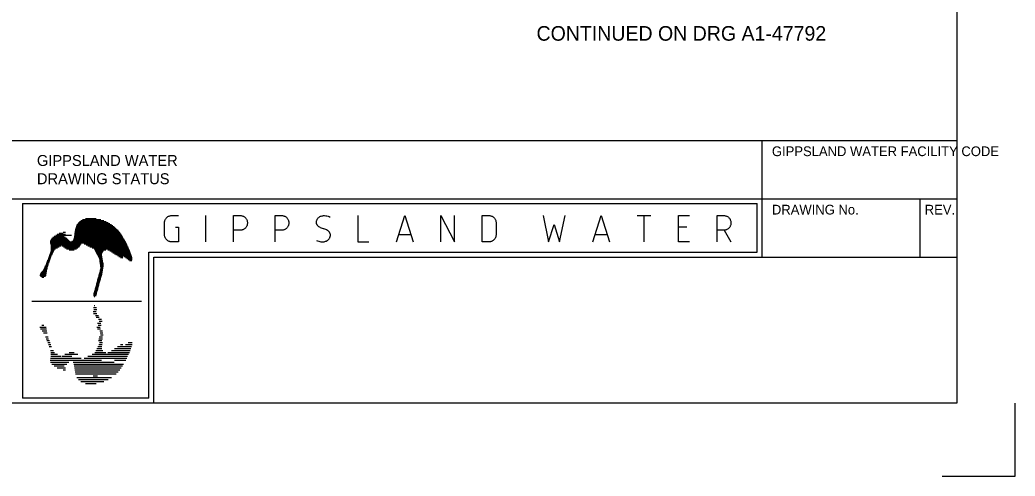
# Model space of a CAD drawing. Extents: x 0 to 841, y 0 to 594.
# Drawn here: x 636.5 to 841, y 0 to 93.8 of the extents above; entities that cross this region are included whole.
import ezdxf

# ---------------------------------------------------------------- set-up
doc = ezdxf.new("R2010")
doc.units = 0
doc.layers.add('A1BORDER', color=7, linetype='Continuous')
doc.layers.add('Level 1', color=7, linetype='Continuous')

msp = doc.modelspace()

# ---------------------------------------------------------------- linework, layer by layer
at = {"layer": 'A1BORDER'}
for p, q in [((829, 581), (829, 15)), ((592.5, 69), (829, 69)), ((789, 45), (789, 69)), ((28, 57), (829, 57)), ((637, 56), (788, 56)), ((637, 56), (637, 16)), ((788, 46), (788, 56)), ((821.5, 45), (821.5, 57)), ((648.03, 51.32), (655.85, 51.32)), ((648.12, 51.52), (655.59, 51.52)), ((648.23, 51.72), (655.31, 51.72)), ((648.37, 51.92), (655, 51.92)), ((648.53, 52.12), (654.64, 52.12)), ((648.74, 52.32), (654.24, 52.32)), ((649.02, 52.52), (653.76, 52.52)), ((649.39, 52.72), (653.15, 52.72)), ((650.01, 52.92), (652.2, 52.92)), ((643.26, 49.12), (645.9, 49.12)), ((643.54, 49.32), (645.57, 49.32)), ((643.85, 49.52), (647.09, 49.52)), ((644.18, 49.72), (645.89, 49.72)), ((644.54, 49.92), (645.36, 49.92)), ((645.37, 50.12), (645.86, 50.12)), ((647.63, 49.12), (657.68, 49.12)), ((647.66, 49.32), (657.57, 49.32)), ((647.69, 49.52), (657.44, 49.52)), ((647.71, 49.72), (657.31, 49.72)), ((647.75, 49.92), (657.17, 49.92)), ((647.78, 50.12), (657.02, 50.12)), ((647.81, 50.32), (656.86, 50.32)), ((647.85, 50.52), (656.69, 50.52)), ((647.88, 50.72), (656.5, 50.72)), ((647.91, 50.92), (656.3, 50.92)), ((647.96, 51.12), (656.08, 51.12)), ((642.73, 48.12), (658.25, 48.12)), ((642.74, 47.92), (658.35, 47.92)), ((642.75, 48.32), (646.79, 48.32)), ((642.79, 47.72), (649.08, 47.72)), ((642.81, 48.52), (646.55, 48.52)), ((642.83, 47.52), (648.95, 47.52)), ((642.85, 47.31), (644.88, 47.31)), ((642.87, 47.12), (644.57, 47.12)), ((642.9, 48.72), (646.37, 48.72)), ((643.04, 48.92), (646.16, 48.92)), ((645.14, 47.31), (648.83, 47.31)), ((645.49, 47.12), (648.67, 47.12)), ((647.19, 48.32), (658.14, 48.32)), ((647.42, 48.52), (658.03, 48.52)), ((647.54, 48.72), (657.92, 48.72)), ((647.61, 48.92), (657.8, 48.92)), ((649.72, 47.72), (658.45, 47.72)), ((650.12, 47.52), (658.55, 47.52)), ((650.48, 47.31), (658.64, 47.31)), ((650.87, 47.12), (658.73, 47.12)), ((642.43, 45.12), (642.9, 45.12)), ((642.5, 45.32), (643, 45.32)), ((642.57, 45.52), (643.1, 45.52)), ((642.65, 45.72), (643.2, 45.72)), ((642.72, 45.92), (643.3, 45.92)), ((642.79, 46.12), (643.4, 46.12)), ((642.84, 46.32), (643.5, 46.32)), ((642.87, 46.52), (643.6, 46.52)), ((642.88, 46.92), (644.23, 46.92)), ((642.88, 46.72), (643.83, 46.72)), ((645.76, 46.92), (648.42, 46.92)), ((646.05, 46.72), (648.11, 46.72)), ((646.62, 46.52), (647.67, 46.52)), ((651.36, 46.92), (658.82, 46.92)), ((651.76, 46.72), (658.9, 46.72)), ((651.88, 46.52), (654.15, 46.52)), ((651.99, 46.32), (653.71, 46.32)), ((652.1, 46.12), (653.52, 46.12)), ((652.2, 45.92), (653.4, 45.92)), ((652.31, 45.72), (653.33, 45.72)), ((652.41, 45.52), (653.31, 45.52)), ((652.5, 45.32), (653.34, 45.32)), ((652.6, 45.12), (653.38, 45.12)), ((654.57, 46.52), (658.99, 46.52)), ((655, 46.32), (659.07, 46.32)), ((655.31, 46.12), (659.14, 46.12)), ((655.62, 45.92), (659.22, 45.92)), ((655.93, 45.72), (659.29, 45.72)), ((656.24, 45.52), (659.35, 45.52)), ((656.55, 45.32), (659.42, 45.32)), ((656.86, 45.12), (657.74, 45.12)), ((657.91, 45.12), (659.48, 45.12)), ((663, 46), (788, 46)), ((663, 16), (663, 46)), ((664, 45), (829, 45)), ((664, 15), (664, 45)), ((641.64, 43.12), (642.25, 43.12)), ((641.73, 43.32), (642.3, 43.32)), ((641.82, 43.51), (642.35, 43.51)), ((641.91, 43.72), (642.41, 43.72)), ((641.99, 43.92), (642.48, 43.92)), ((642.06, 44.12), (642.55, 44.12)), ((642.13, 44.32), (642.62, 44.32)), ((642.21, 44.52), (642.69, 44.52)), ((642.28, 44.72), (642.76, 44.72)), ((642.35, 44.92), (642.83, 44.92)), ((652.69, 44.92), (653.41, 44.92)), ((652.78, 44.72), (653.44, 44.72)), ((652.83, 44.52), (653.48, 44.52)), ((652.86, 44.32), (653.53, 44.32)), ((652.89, 44.12), (653.57, 44.12)), ((652.91, 43.92), (653.62, 43.92)), ((652.94, 43.72), (653.67, 43.72)), ((652.97, 43.51), (653.71, 43.51)), ((653, 43.32), (653.69, 43.32)), ((653.02, 43.12), (653.67, 43.12)), ((657.17, 44.92), (657.68, 44.92)), ((657.51, 44.72), (657.54, 44.72)), ((658.19, 44.92), (659.54, 44.92)), ((658.47, 44.72), (659.59, 44.72)), ((658.75, 44.52), (659.58, 44.52)), ((659.02, 44.32), (659.47, 44.32)), ((640.62, 41.32), (641.88, 41.32)), ((640.63, 41.52), (641.93, 41.52)), ((640.72, 41.12), (641.73, 41.12)), ((640.73, 41.72), (641.95, 41.72)), ((640.9, 41.92), (641.97, 41.92)), ((641.03, 40.92), (641.43, 40.92)), ((641.1, 42.12), (642, 42.12)), ((641.25, 42.31), (642.04, 42.31)), ((641.37, 42.52), (642.09, 42.52)), ((641.46, 42.72), (642.15, 42.72)), ((641.55, 42.92), (642.2, 42.92)), ((652.57, 40.92), (653.2, 40.92)), ((652.63, 41.12), (653.26, 41.12)), ((652.68, 41.32), (653.31, 41.32)), ((652.74, 41.52), (653.37, 41.52)), ((652.79, 41.72), (653.41, 41.72)), ((652.85, 41.92), (653.45, 41.92)), ((652.9, 42.12), (653.49, 42.12)), ((652.95, 42.31), (653.53, 42.31)), ((652.99, 42.52), (653.57, 42.52)), ((653.03, 42.72), (653.61, 42.72)), ((653.05, 42.92), (653.64, 42.92)), ((652.03, 38.92), (652.66, 38.92)), ((652.09, 39.12), (652.72, 39.12)), ((652.14, 39.32), (652.77, 39.32)), ((652.2, 39.52), (652.82, 39.52)), ((652.25, 39.72), (652.88, 39.72)), ((652.3, 39.92), (652.93, 39.92)), ((652.36, 40.12), (652.99, 40.12)), ((652.41, 40.32), (653.04, 40.32)), ((652.47, 40.52), (653.1, 40.52)), ((652.52, 40.72), (653.15, 40.72)), ((651.63, 37.32), (652.23, 37.32)), ((651.64, 37.12), (652.17, 37.12)), ((651.65, 37.52), (652.28, 37.52)), ((651.71, 37.72), (652.34, 37.72)), ((651.76, 37.92), (652.39, 37.92)), ((651.79, 36.92), (651.9, 36.92)), ((651.82, 38.12), (652.44, 38.12)), ((651.87, 38.32), (652.5, 38.32)), ((651.92, 38.52), (652.55, 38.52)), ((651.98, 38.72), (652.61, 38.72)), ((638.93, 35.98), (661.47, 35.98)), ((651.79, 35.04), (651.9, 35.04)), ((651.54, 33.84), (652.17, 33.84)), ((651.63, 34.64), (652.23, 34.64)), ((651.65, 33.44), (652.28, 33.44)), ((651.71, 34.24), (652.34, 34.24)), ((652.03, 33.04), (652.66, 33.04)), ((641.03, 31.04), (641.43, 31.04)), ((652.14, 32.64), (652.77, 32.64)), ((652.47, 31.44), (653.1, 31.44)), ((652.57, 31.04), (653.2, 31.04)), ((652.66, 32.24), (653.29, 32.24)), ((652.77, 31.84), (653.4, 31.84)), ((640.62, 30.64), (641.88, 30.64)), ((640.73, 30.24), (641.95, 30.24)), ((641.1, 29.84), (642, 29.84)), ((641.37, 29.44), (642.09, 29.44)), ((641.73, 28.64), (642.3, 28.64)), ((652.34, 30.64), (652.97, 30.64)), ((652.45, 30.24), (653.07, 30.24)), ((652.77, 28.64), (653.46, 28.64)), ((652.9, 29.84), (653.49, 29.84)), ((652.99, 29.44), (653.57, 29.44)), ((653.05, 29.04), (653.64, 29.04)), ((641.91, 28.24), (642.41, 28.24)), ((642.06, 27.84), (642.55, 27.84)), ((642.21, 27.44), (642.69, 27.44)), ((642.35, 27.04), (642.83, 27.04)), ((642.5, 26.64), (643, 26.64)), ((652.5, 26.64), (653.34, 26.64)), ((652.66, 27.84), (653.35, 27.84)), ((652.69, 27.04), (653.41, 27.04)), ((652.72, 28.24), (653.44, 28.24)), ((652.83, 27.44), (653.48, 27.44)), ((656.55, 26.64), (659.42, 26.64)), ((657.17, 27.04), (657.68, 27.04)), ((658.19, 27.04), (659.54, 27.04)), ((658.75, 27.44), (659.58, 27.44)), ((642.79, 25.84), (643.4, 25.84)), ((642.85, 24.65), (644.88, 24.65)), ((642.87, 25.44), (643.6, 25.44)), ((642.88, 25.04), (644.23, 25.04)), ((645.14, 24.65), (647.18, 24.65)), ((645.76, 25.04), (648.42, 25.04)), ((646.62, 25.44), (647.67, 25.44)), ((650.48, 24.65), (658.64, 24.65)), ((651.36, 25.04), (658.82, 25.04)), ((651.88, 25.44), (654.15, 25.44)), ((652.1, 25.84), (653.52, 25.84)), ((652.31, 26.24), (653.33, 26.24)), ((654.57, 25.44), (658.99, 25.44)), ((655.31, 25.84), (659.14, 25.84)), ((655.93, 26.24), (659.29, 26.24)), ((642.73, 23.84), (653.27, 23.84)), ((642.79, 24.24), (649.08, 24.24)), ((642.81, 23.44), (646.55, 23.44)), ((643.04, 23.04), (646.16, 23.04)), ((643.54, 22.64), (645.57, 22.64)), ((647.42, 23.44), (655.89, 23.44)), ((647.61, 23.04), (657.8, 23.04)), ((647.66, 22.64), (657.57, 22.64)), ((649.72, 24.24), (658.45, 24.24)), ((655.94, 23.84), (658.25, 23.84)), ((644.18, 22.24), (645.89, 22.24)), ((645.37, 21.84), (645.86, 21.84)), ((647.71, 22.24), (657.31, 22.24)), ((647.78, 21.84), (657.02, 21.84)), ((647.85, 21.44), (656.69, 21.44)), ((647.91, 21.04), (656.3, 21.04)), ((651.57, 20.64), (652.44, 20.64)), ((648.23, 20.24), (655.31, 20.24)), ((648.53, 19.84), (654.64, 19.84)), ((649.02, 19.44), (653.76, 19.44)), ((650.01, 19.04), (652.2, 19.04)), ((829, 15), (28, 15)), ((663, 16), (637, 16)), ((829, 15), (829, 15)), ((841, 0), (841, 15)), ((826, 0), (841, 0))]:
    msp.add_line(p, q, dxfattribs=at)
for points in [[(668.49, 51.15), (669.06, 51.15), (669.06, 48.16), (667.64, 48.16), (667.51, 48.16), (667.39, 48.18), (667.28, 48.21), (667.15, 48.25), (667.04, 48.3), (666.93, 48.36), (666.82, 48.43), (666.73, 48.51), (666.64, 48.6), (666.55, 48.7), (666.48, 48.8), (666.41, 48.91), (666.35, 49.02), (666.31, 49.14), (666.27, 49.27), (666.24, 49.39), (666.22, 49.52), (666.22, 49.66), (666.22, 52.05), (666.22, 52.18), (666.24, 52.31), (666.27, 52.43), (666.31, 52.56), (666.35, 52.67), (666.41, 52.79), (666.48, 52.9), (666.55, 53), (666.64, 53.1), (666.73, 53.19), (666.82, 53.27), (666.93, 53.34), (667.04, 53.4), (667.15, 53.45), (667.28, 53.49), (667.39, 53.52), (667.51, 53.54), (667.64, 53.54), (669.06, 53.54)], [(674.74, 48.16), (674.74, 53.54)], [(680.42, 48.16), (680.42, 53.54), (681.84, 53.54), (681.96, 53.54), (682.08, 53.52), (682.2, 53.49), (682.32, 53.45), (682.43, 53.4), (682.54, 53.34), (682.65, 53.27), (682.74, 53.19), (682.84, 53.1), (682.92, 53), (682.99, 52.9), (683.06, 52.79), (683.12, 52.67), (683.17, 52.56), (683.21, 52.43), (683.23, 52.31), (683.25, 52.18), (683.26, 52.05), (683.25, 51.91), (683.23, 51.78), (683.21, 51.66), (683.17, 51.53), (683.12, 51.42), (683.06, 51.3), (682.99, 51.19), (682.92, 51.09), (682.84, 50.99), (682.74, 50.9), (682.65, 50.82), (682.54, 50.75), (682.43, 50.69), (682.32, 50.64), (682.2, 50.6), (682.08, 50.57), (681.96, 50.55), (681.84, 50.55), (680.42, 50.55)], [(688.93, 48.16), (688.93, 53.54), (690.35, 53.54), (690.47, 53.54), (690.59, 53.52), (690.71, 53.49), (690.83, 53.45), (690.94, 53.4), (691.05, 53.34), (691.16, 53.27), (691.26, 53.19), (691.35, 53.1), (691.43, 53), (691.51, 52.9), (691.57, 52.79), (691.63, 52.67), (691.68, 52.56), (691.72, 52.43), (691.75, 52.31), (691.76, 52.18), (691.77, 52.05), (691.76, 51.91), (691.75, 51.78), (691.72, 51.66), (691.68, 51.53), (691.63, 51.42), (691.57, 51.3), (691.51, 51.19), (691.43, 51.09), (691.35, 50.99), (691.26, 50.9), (691.16, 50.82), (691.05, 50.75), (690.94, 50.69), (690.83, 50.64), (690.71, 50.6), (690.59, 50.57), (690.47, 50.55), (690.35, 50.55), (688.93, 50.55)], [(697.45, 48.46), (697.67, 48.36), (697.9, 48.27), (698.12, 48.21), (698.36, 48.17), (698.6, 48.16), (698.84, 48.16), (698.87, 48.16), (699.03, 48.18), (699.18, 48.21), (699.33, 48.26), (699.48, 48.32), (699.62, 48.4), (699.72, 48.46), (699.81, 48.53), (699.9, 48.61), (699.98, 48.69), (700.05, 48.78), (700.11, 48.88), (700.17, 48.99), (700.22, 49.09), (700.25, 49.21), (700.28, 49.32), (700.29, 49.36), (700.3, 49.44), (700.3, 49.52), (700.3, 49.61), (700.29, 49.69), (700.27, 49.77), (700.25, 49.86), (700.22, 49.93), (700.18, 50.01), (700.14, 50.09), (700.09, 50.15), (700.04, 50.21), (700.01, 50.25), (699.85, 50.39), (699.69, 50.51), (699.52, 50.61), (699.34, 50.7), (699.15, 50.78), (698.95, 50.83), (698.87, 50.85), (698.68, 50.9), (698.49, 50.96), (698.3, 51.04), (698.12, 51.14), (697.96, 51.26), (697.8, 51.39), (697.73, 51.45), (697.67, 51.51), (697.62, 51.57), (697.58, 51.64), (697.53, 51.71), (697.5, 51.79), (697.47, 51.87), (697.46, 51.95), (697.44, 52.04), (697.43, 52.12), (697.43, 52.21), (697.44, 52.29), (697.45, 52.35), (697.47, 52.46), (697.51, 52.58), (697.55, 52.69), (697.61, 52.79), (697.67, 52.89), (697.74, 52.99), (697.82, 53.07), (697.9, 53.15), (697.99, 53.23), (698.02, 53.24), (698.15, 53.33), (698.3, 53.4), (698.44, 53.45), (698.6, 53.5), (698.75, 53.52), (698.87, 53.54), (699.11, 53.55), (699.35, 53.53), (699.58, 53.49), (699.82, 53.43), (700.04, 53.35), (700.27, 53.25)], [(705.96, 53.54), (705.96, 48.16), (708.23, 48.16)], [(713.91, 48.16), (715.61, 53.54), (717.32, 48.16)], [(722.99, 48.16), (722.99, 53.54), (725.83, 48.16), (725.83, 53.54)], [(731.52, 48.16), (731.52, 53.54), (732.94, 53.54), (733.06, 53.54), (733.18, 53.52), (733.3, 53.49), (733.42, 53.45), (733.53, 53.4), (733.64, 53.34), (733.75, 53.27), (733.84, 53.19), (733.94, 53.1), (734.02, 53), (734.09, 52.9), (734.16, 52.79), (734.22, 52.67), (734.27, 52.56), (734.31, 52.43), (734.33, 52.31), (734.35, 52.18), (734.36, 52.05), (734.36, 49.66), (734.35, 49.52), (734.33, 49.39), (734.31, 49.27), (734.27, 49.14), (734.22, 49.02), (734.16, 48.91), (734.09, 48.8), (734.02, 48.7), (733.94, 48.6), (733.84, 48.51), (733.75, 48.43), (733.64, 48.36), (733.53, 48.3), (733.42, 48.25), (733.3, 48.21), (733.18, 48.18), (733.06, 48.16), (732.94, 48.16), (731.52, 48.16)], [(744.01, 53.54), (745.14, 48.16), (746.28, 51.75), (747.41, 48.16), (748.55, 53.54)], [(754.22, 48.16), (755.92, 53.54), (757.63, 48.16)], [(763.31, 53.54), (766.15, 53.54)], [(764.73, 53.54), (764.73, 48.16)], [(774.09, 48.16), (771.82, 48.16), (771.82, 53.54), (774.09, 53.54)], [(779.78, 48.16), (779.78, 53.54), (781.2, 53.54), (781.32, 53.54), (781.44, 53.52), (781.56, 53.49), (781.68, 53.45), (781.79, 53.4), (781.9, 53.34), (782.01, 53.27), (782.1, 53.19), (782.2, 53.1), (782.28, 53), (782.35, 52.9), (782.42, 52.79), (782.48, 52.67), (782.53, 52.56), (782.56, 52.43), (782.59, 52.31), (782.61, 52.18), (782.61, 52.05), (782.61, 51.91), (782.59, 51.78), (782.56, 51.66), (782.53, 51.53), (782.48, 51.42), (782.42, 51.3), (782.35, 51.19), (782.28, 51.09), (782.2, 50.99), (782.1, 50.9), (782.01, 50.82), (781.9, 50.75), (781.79, 50.69), (781.68, 50.64), (781.56, 50.6), (781.44, 50.57), (781.32, 50.55), (781.2, 50.55), (779.78, 50.55)], [(773.53, 51.15), (771.82, 51.15)], [(714.48, 49.66), (716.75, 49.66)], [(754.79, 49.66), (757.06, 49.66)], [(781.2, 50.55), (782.61, 48.16)]]:
    msp.add_lwpolyline(points, dxfattribs=at)

# ---------------------------------------------------------------- texts
for s, height, p in [('GIPPSLAND WATER FACILITY CODE', 2, (791.03, 65.77)), ('GIPPSLAND WATER', 2.25, (640, 63.75)), ('DRAWING STATUS', 2.25, (640, 60)), ('DRAWING No.', 2, (791.03, 53.77)), ('REV.', 2, (822.43, 53.77))]:
    msp.add_text(s, height=height, dxfattribs=at).set_placement(p)
at = {"layer": 'Level 1'}
msp.add_text('CONTINUED ON DRG A1-47792', height=3, dxfattribs=at).set_placement((742.66, 89.5))

doc.saveas('drawing.dxf')
